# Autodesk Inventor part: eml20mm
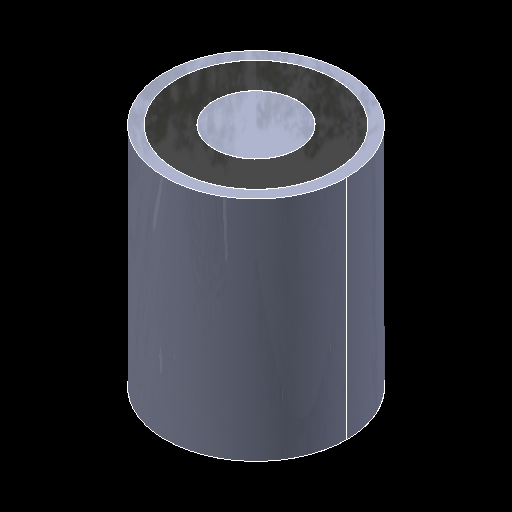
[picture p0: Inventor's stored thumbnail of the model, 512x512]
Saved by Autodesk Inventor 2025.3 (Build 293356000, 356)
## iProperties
Created: 2023-09
Part Number: eml20mm
Project: COMMON
Material: Generic
Catalog Web Link: https://www.janelia.org/
Vendor: HHMI: JRC - JET
Document SubType Name: Modeling
Designer: sohna
Density: 1 g/cm^3
Appearance: Default
RuleStatus: InUse
AfterDocSave0: file://Part Number Cleaner
Title: Standard
Author: sohna
Revision Number: 0
LAB/DEPT: COMMON
REQUESTING SCIENTIST: COMMON
DESIGN DEPARTMENT: HHMI: JRC - ID&F
ALTERED ITEM PART NUMBER: N/A
ALTERED ITEM VENDOR: N/A
ALTERED ITEM DESCRIPTION: N/A
Author: DavidPromnitz
Title: R:\Permanent Electromagnets\Updated Specs and Drawings\EML20mm\EML20mm.IGS
Description: SolidWorks IGES file using analytic representation for surfaces
Sending System: SolidWorks 2023
Preprocessor: SolidWorks 2023
Minimum Resolution: 0.0
Sending System Product ID: EML20mm.SLDPRT
Receiving System Product ID: EML20mm.SLDPRT
Sent Units: Millimeter
Translation Standard: IGES 5.3
Model Creation Time: 2023-09-29
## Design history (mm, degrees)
feature "Composite1"
body "Srf1"
